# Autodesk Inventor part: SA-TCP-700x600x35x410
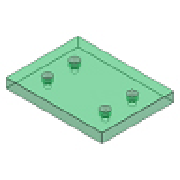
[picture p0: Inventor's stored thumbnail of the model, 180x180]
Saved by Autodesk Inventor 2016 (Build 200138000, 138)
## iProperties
Created: 2015-02
Part Number: SA-TCP-700x600x35x410
Material: S 55 C
Description: Top Clamping Plate
Document SubType Name: Modeling
Designer: Sandeep
Standard Revision: 1
Manufacturer: FUTABA
Language: en-US
Size Designation: 700x600x35x410
Categories: <MemberInstance><Categories><Category DisplayName="Mold" InternalName="349578f2-f4d4-4954-8c09-8e99297a61c0" Mnemonic="MOLD"><Category DisplayName="Mold Plates"
Density: 7.85 g/cm^3
Appearance: Clear - Green 1
IsCustomPart: 1
Author: Sandeep
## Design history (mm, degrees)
sketch "Sketch1"
  geometry: L1 (-300, 350)-(300, 350); L2 (300, 350)-(300, -350); L3 (300, -350)-(-300, -350); L4 (-300, -350)-(-300, 350); 3 further points
  constraints: 8 end point, 2 midpoint, 2 parallel, 1 horizontal, 1 horizontal alignment, 1 perpendicular, 1 vertical alignment
  dimensions: "d72" = 600 distance between parallel lines of L2 L4 (= W_); "d73" = 700 distance between parallel lines of L3 L1 (= L)
extrude "Extrusion1" new body sketch "Sketch1" distance "d20" = 35 (= H_); taper "d30" = 0 deg
feature "Sculpt1"
feature "Sculpt2"
thread "Thread1" dims "d74" = 0, "d75" = 0
body "Solid1"
sketch "Sketch2"
  geometry: 2 further points
  dimensions: "d53" = 205 horizontal distance of point (0, 0) point (-205, 243) (= 0.5 x S1_W); "d54" = 243 vertical distance of point (0, 0) point (-205, 243) (= 0.5 x S1_L)
hole "Hole1" sketch "Sketch2" diameter "d55" = 18 (= S1_d1); stored, may be unused: countersink angle "d59" = 90 deg, drill point angle "d61" = 0 deg; dims "d56" = 6, "d57" = 26 (= S1_d2), "d58" = 17.5 (= S1_k), "d60" = 35 (= H_)
pattern_linear "Rectangular Pattern1" dims "d64" = 243 (computed from S1_L, Ns)
chamfer "Chamfer1" distance "d68" = 0.5; stored, may be unused: second distance "d69" = 2, angle "d71" = 45 deg
feature "Surface1"
body "Srf1"
feature "Surface2"
body "Srf2"
other parameters: "L" = 700 [user parameter; used in 1 equation term], "W_" = 600 [user parameter; used in 1 equation term], "H_" = 35 [user parameter; used in 2 equation terms], "S1_d1" = 18 [user parameter; used in 1 equation term], "S1_d2" = 26 [user parameter; used in 1 equation term], "S1_k" = 17.5 [user parameter; used in 1 equation term], "S1_L" = 486 [user parameter; used in 2 equation terms]
